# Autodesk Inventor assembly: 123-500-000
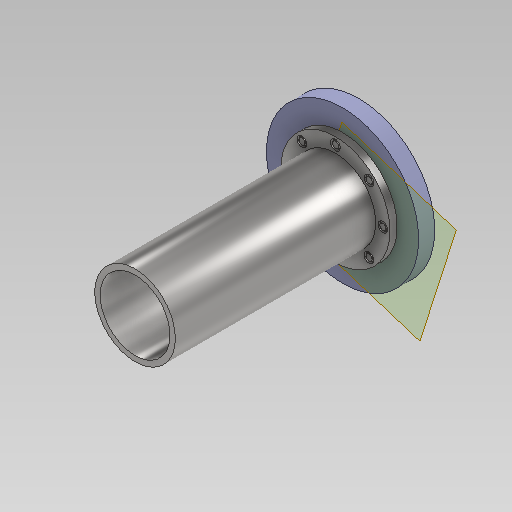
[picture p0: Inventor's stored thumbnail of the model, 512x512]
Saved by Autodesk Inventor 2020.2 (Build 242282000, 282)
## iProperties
Manager: www.cadconsulting.pl
Company: Fabian Stasiak CAD Consulting
Created: 2019-11
Part Number: 123-500-000
Document SubType Name: Assembly
Designer: F.Stasiak
Author: F.Stasiak
Subject: Zbiór ćwiczeń. Autodesk Inventor 2020. Kurs podstawowy
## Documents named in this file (4)
- C:\2020_Kurs_podstawowy\R6 Zespoły\BOM\123-500-000.iam
- C:\2020_Kurs_podstawowy\R6 Zespoły\BOM\123-500-001.ipt
- C:\2020_Kurs_podstawowy\R6 Zespoły\BOM\123-500-002.ipt
- C:\2020_Kurs_podstawowy\R6 Zespoły\BOM\123-500-000\Design Accelerator\Połączenie gwintowe1.iam
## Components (10 placed, 3 different names)
1. 123-500-001:1 — Równoległe:1, Równoległe:2, Zestawiające:1, Zestawiające:2, Zestawiające:3
2. 123-500-002:1 — Równoległe:1, Równoległe:2, Zestawiające:1
3. Połączenie gwintowe:1 [sub-assembly] — Zestawiające:2, Zestawiające:3
4. Połączenie gwintowe:2 [sub-assembly]
5. Połączenie gwintowe:3 [sub-assembly]
6. Połączenie gwintowe:4 [sub-assembly]
7. Połączenie gwintowe:5 [sub-assembly]
8. Połączenie gwintowe:6 [sub-assembly]
9. Połączenie gwintowe:7 [sub-assembly]
10. Połączenie gwintowe:8 [sub-assembly]
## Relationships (5: Mate 3, Flush 2)
- Równoległe:1 [Flush]: 123-500-001:1 ↔ 123-500-002:1
- Równoległe:2 [Flush]: 123-500-001:1 ↔ 123-500-002:1
- Zestawiające:1 [Mate]: 123-500-001:1 ↔ 123-500-002:1
- Zestawiające:2 [Mate]: 123-500-001:1 ↔ Połączenie gwintowe:1
- Zestawiające:3 [Mate]: 123-500-001:1 ↔ Połączenie gwintowe:1
